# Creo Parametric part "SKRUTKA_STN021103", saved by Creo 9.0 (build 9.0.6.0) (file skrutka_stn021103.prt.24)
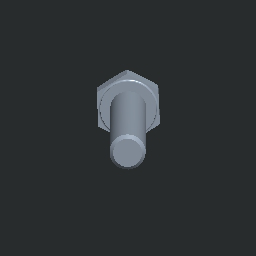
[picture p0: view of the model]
Units: Custom; MM, KILOGRAM, SECS
Materials in the file: OCEL_N

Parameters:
  WERKSTOFF = "8.8"
  KATEGORIE = "4"
  NAZOV = "SKRUTKA_STN021103"
  NORMA = "STN 02 1103"
  N1 = "021"
  N2 = "21"
  N3 = "1"
  CISLO_VYKRESU = "SKRUTKA_STN021103"
  PTC_MATERIAL_NAME = "OCEL_N"
  PLACEMENT = "A"

Other parameters: HMOTNOST, HUSTOTA, HMOTNOST_1, D50, D2, D7, D25, D30, THREADS_PER_INCH

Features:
  1. chamfer
  2. datum plane "DTM1"
  3. protrusion
  4. datum plane "DTM6"
  5. cut
  6. datum plane "DTM7"
  7. cut
  8. datum plane "DTM8"
  9. datum plane "DTM9"

Layers: BEZUGSEBENEN, KONSTRUKTIONSELEMENTE, NORMTEILE

Family table entries: SKRUTKA_M3X4, SKRUTKA_STN021103, value(d_val), value(i_val), SKRUTKA_M3X5, SKRUTKA_STN021103, SKRUTKA_M3X6, SKRUTKA_STN021103, SKRUTKA_M3X8, SKRUTKA_STN021103, 2/ , SKRUTKA_M3X10, SKRUTKA_STN021103, 2/$, SKRUTKA_M3X12, SKRUTKA_STN021103, 2/(, SKRUTKA_M3X16, SKRUTKA_STN021103, 2/0, SKRUTKA_M3X20, SKRUTKA_STN021103, 2/4, SKRUTKA_M3X25, SKRUTKA_STN021103, 2/9, SKRUTKA_M3X30, SKRUTKA_STN021103, 2/>, SKRUTKA_M4X8, SKRUTKA_STN021103, 2/ , SKRUTKA_M4X10, SKRUTKA_STN021103, 2/$, SKRUTKA_M4X12, SKRUTKA_STN021103, 2/(, SKRUTKA_M4X16, SKRUTKA_STN021103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

Surfaces: 10 plane, 4 cone, 3 cylinder, 2 torus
